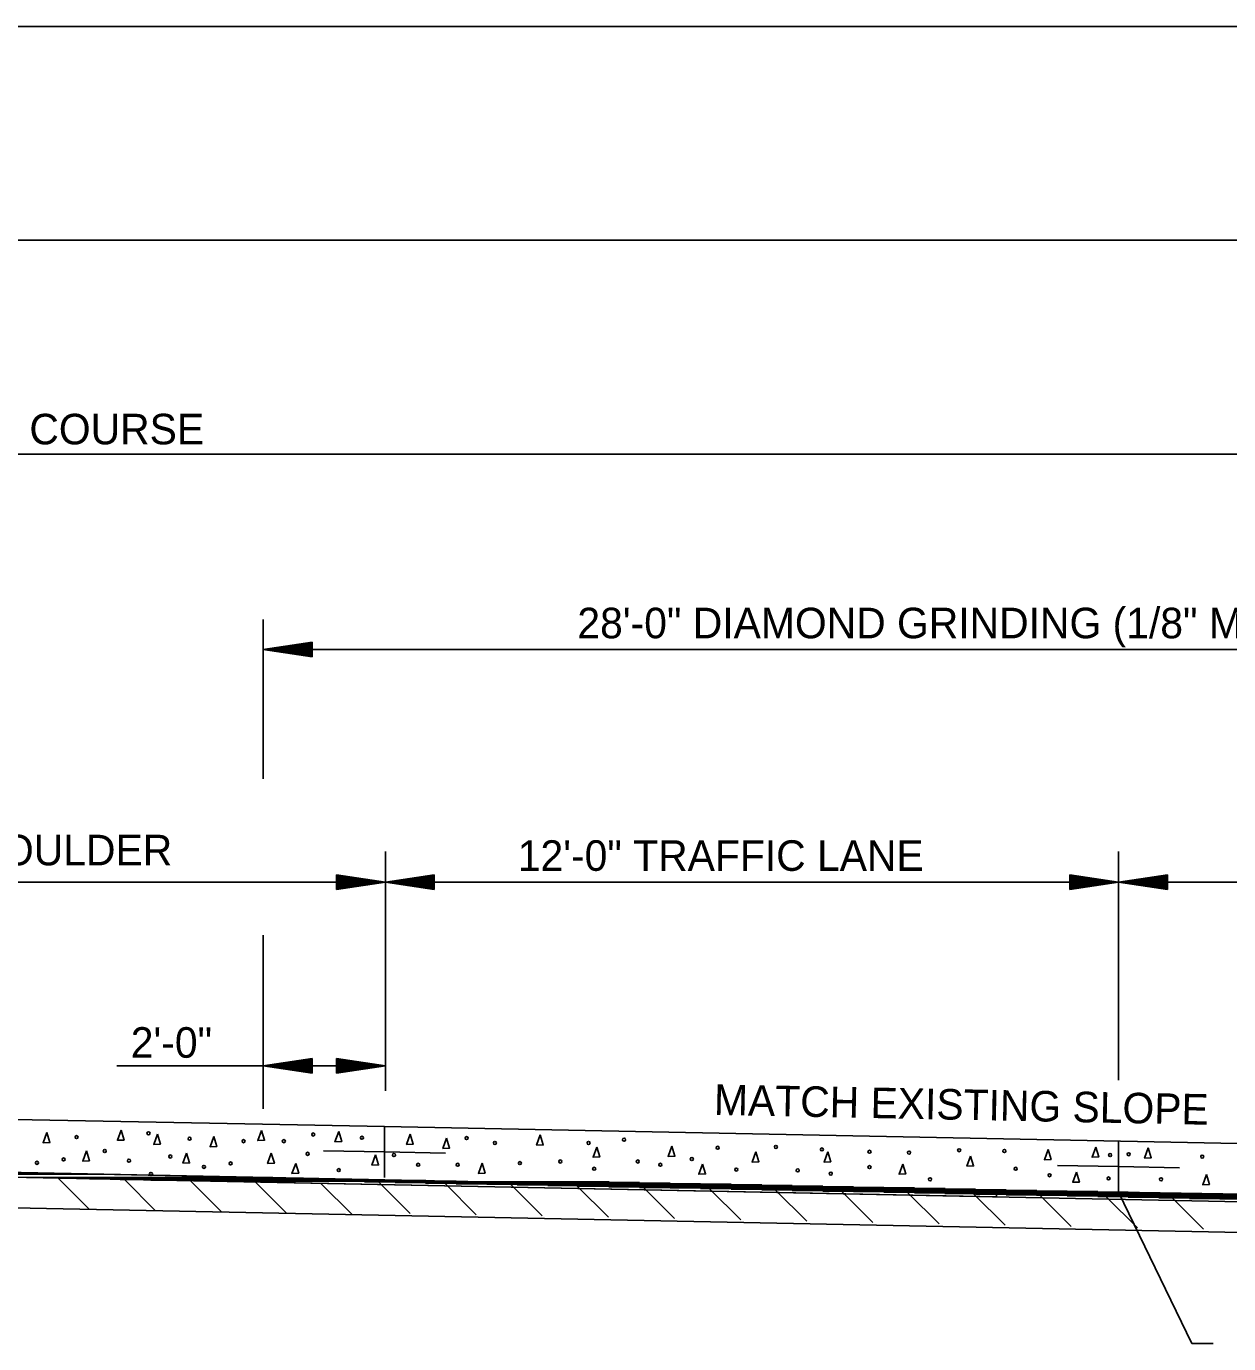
# Model space of a CAD drawing. Extents: x 60325 to 61047, y 53669 to 53767.
# Drawn here: x 60578.67 to 60598.35, y 53690.57 to 53712.12 of the extents above; entities that cross this region are included whole.
import ezdxf

# ---------------------------------------------------------------- set-up
doc = ezdxf.new("R2010")
doc.units = 0
doc.layers.add('R_Border', color=7, linetype='Continuous')
doc.layers.add('R_Border Prem', color=7, linetype='Continuous')

msp = doc.modelspace()

# ---------------------------------------------------------------- linework, layer by layer
at = {"layer": 'R_Border'}
for p, q in [((60582.545, 53699.814), (60582.545, 53702.419)), ((60583.345, 53702.049), (60582.545, 53701.929)), ((60583.345, 53702.029), (60582.679, 53701.929)), ((60583.345, 53701.809), (60583.345, 53702.049)), ((60610.545, 53701.929), (60582.545, 53701.929)), ((60583.345, 53701.809), (60582.545, 53701.929)), ((60583.345, 53701.829), (60582.679, 53701.929)), ((60583.345, 53702.009), (60582.816, 53701.929)), ((60583.345, 53701.85), (60582.816, 53701.929)), ((60583.345, 53701.989), (60582.95, 53701.929)), ((60583.345, 53701.87), (60582.95, 53701.929)), ((60583.345, 53701.969), (60583.085, 53701.929)), ((60583.345, 53701.891), (60583.085, 53701.929)), ((60583.345, 53701.948), (60583.219, 53701.929)), ((60583.345, 53701.911), (60583.219, 53701.929)), ((60584.545, 53694.884), (60584.545, 53698.624)), ((60596.545, 53694.884), (60596.545, 53698.624)), ((60583.745, 53698.244), (60584.545, 53698.124)), ((60583.745, 53698.244), (60583.745, 53698.004)), ((60583.745, 53698.224), (60584.412, 53698.124)), ((60583.745, 53698.204), (60584.274, 53698.124)), ((60583.745, 53698.184), (60584.141, 53698.124)), ((60583.745, 53698.163), (60584.005, 53698.124)), ((60583.745, 53698.143), (60583.872, 53698.124)), ((60585.345, 53698.244), (60584.545, 53698.124)), ((60585.345, 53698.224), (60584.679, 53698.124)), ((60585.345, 53698.204), (60584.816, 53698.124)), ((60585.345, 53698.184), (60584.95, 53698.124)), ((60585.345, 53698.164), (60585.085, 53698.124)), ((60585.345, 53698.143), (60585.219, 53698.124)), ((60585.345, 53698.004), (60585.345, 53698.244)), ((60595.745, 53698.244), (60596.545, 53698.124)), ((60595.745, 53698.244), (60595.745, 53698.004)), ((60595.745, 53698.224), (60596.412, 53698.124)), ((60595.745, 53698.204), (60596.274, 53698.124)), ((60595.745, 53698.184), (60596.141, 53698.124)), ((60595.745, 53698.163), (60596.005, 53698.124)), ((60595.745, 53698.143), (60595.872, 53698.124)), ((60597.345, 53698.244), (60596.545, 53698.124)), ((60597.345, 53698.224), (60596.679, 53698.124)), ((60597.345, 53698.204), (60596.816, 53698.124)), ((60597.345, 53698.184), (60596.95, 53698.124)), ((60597.345, 53698.164), (60597.085, 53698.124)), ((60597.345, 53698.143), (60597.219, 53698.124)), ((60597.345, 53698.004), (60597.345, 53698.244)), ((60572.545, 53698.124), (60584.545, 53698.124)), ((60583.745, 53698.004), (60584.545, 53698.124)), ((60583.745, 53698.085), (60584.005, 53698.124)), ((60583.745, 53698.045), (60584.274, 53698.124)), ((60583.745, 53698.024), (60584.412, 53698.124)), ((60583.745, 53698.065), (60584.141, 53698.124)), ((60583.745, 53698.106), (60583.872, 53698.124)), ((60585.345, 53698.004), (60584.545, 53698.124)), ((60596.545, 53698.124), (60584.545, 53698.124)), ((60585.345, 53698.024), (60584.679, 53698.124)), ((60585.345, 53698.045), (60584.816, 53698.124)), ((60585.345, 53698.065), (60584.95, 53698.124)), ((60585.345, 53698.086), (60585.085, 53698.124)), ((60585.345, 53698.106), (60585.219, 53698.124)), ((60595.745, 53698.004), (60596.545, 53698.124)), ((60595.745, 53698.085), (60596.005, 53698.124)), ((60595.745, 53698.045), (60596.274, 53698.124)), ((60595.745, 53698.024), (60596.412, 53698.124)), ((60595.745, 53698.065), (60596.141, 53698.124)), ((60595.745, 53698.106), (60595.872, 53698.124)), ((60608.545, 53698.124), (60596.545, 53698.124)), ((60597.345, 53698.004), (60596.545, 53698.124)), ((60597.345, 53698.024), (60596.679, 53698.124)), ((60597.345, 53698.045), (60596.816, 53698.124)), ((60597.345, 53698.065), (60596.95, 53698.124)), ((60597.345, 53698.086), (60597.085, 53698.124)), ((60597.345, 53698.106), (60597.219, 53698.124)), ((60582.545, 53694.411), (60582.545, 53697.257)), ((60584.545, 53694.709), (60584.545, 53695.444)), ((60582.545, 53695.118), (60580.151, 53695.118)), ((60583.345, 53695.238), (60582.545, 53695.118)), ((60584.545, 53695.118), (60582.545, 53695.118)), ((60583.345, 53694.998), (60582.545, 53695.118)), ((60583.345, 53695.218), (60582.679, 53695.118)), ((60583.345, 53695.018), (60582.679, 53695.118)), ((60583.345, 53695.197), (60582.816, 53695.118)), ((60583.345, 53695.038), (60582.816, 53695.118)), ((60583.345, 53695.177), (60582.95, 53695.118)), ((60583.345, 53695.058), (60582.95, 53695.118)), ((60583.345, 53695.156), (60583.085, 53695.118)), ((60583.345, 53695.078), (60583.085, 53695.118)), ((60583.345, 53695.136), (60583.219, 53695.118)), ((60583.345, 53695.099), (60583.219, 53695.118)), ((60583.345, 53695.238), (60583.345, 53694.998)), ((60583.745, 53695.238), (60584.545, 53695.118)), ((60583.745, 53695.238), (60583.745, 53694.998)), ((60583.745, 53695.218), (60584.412, 53695.118)), ((60583.745, 53695.197), (60584.274, 53695.118)), ((60583.745, 53695.177), (60584.141, 53695.118)), ((60583.745, 53695.156), (60584.005, 53695.118)), ((60583.745, 53695.136), (60583.872, 53695.118)), ((60583.745, 53694.998), (60584.545, 53695.118)), ((60583.745, 53695.078), (60584.005, 53695.118)), ((60583.745, 53695.038), (60584.274, 53695.118)), ((60583.745, 53695.018), (60584.412, 53695.118)), ((60583.745, 53695.058), (60584.141, 53695.118)), ((60583.745, 53695.099), (60583.872, 53695.118)), ((60584.53, 53694.125), (60584.53, 53693.292)), ((60596.545, 53693.884), (60596.545, 53693.051)), ((60583.53, 53693.728), (60584.53, 53693.708)), ((60584.53, 53693.708), (60585.53, 53693.688)), ((60595.545, 53693.488), (60596.545, 53693.468)), ((60596.545, 53693.468), (60597.545, 53693.448)), ((60597.746, 53690.571), (60596.545, 53693.051)), ((60598.093, 53690.571), (60597.746, 53690.571))]:
    msp.add_line(p, q, dxfattribs=at)
msp.add_lwpolyline([(60582.532, 53694.162), (60584.53, 53694.125), (60610.545, 53693.604)], dxfattribs=at)
at = {"layer": 'R_Border Prem'}
for p, q in [((60618.545, 53712.124), (60524.545, 53712.124)), ((60619.713, 53708.624), (60522.149, 53708.624)), ((60619.713, 53705.124), (60522.149, 53705.124)), ((60582.532, 53694.162), (60572.541, 53694.344)), ((60571.545, 53693.511), (60610.545, 53692.731)), ((60571.545, 53693.431), (60610.545, 53692.651)), ((60575.4, 53693.354), (60579.401, 53693.354)), ((60575.9, 53693.344), (60579.901, 53693.344)), ((60578.704, 53693.288), (60582.705, 53693.288)), ((60579.191, 53693.278), (60579.702, 53692.768)), ((60579.204, 53693.278), (60583.205, 53693.278)), ((60579.704, 53693.268), (60583.705, 53693.268)), ((60580.204, 53693.258), (60584.205, 53693.258)), ((60580.274, 53693.256), (60580.784, 53692.746)), ((60580.704, 53693.248), (60584.705, 53693.248)), ((60581.204, 53693.238), (60585.205, 53693.238)), ((60581.356, 53693.235), (60581.866, 53692.724)), ((60581.704, 53693.228), (60585.705, 53693.228)), ((60582.421, 53693.213), (60582.932, 53692.703)), ((60583.49, 53693.192), (60584.001, 53692.682)), ((60584.204, 53693.218), (60588.205, 53693.218)), ((60584.443, 53693.209), (60584.949, 53692.703)), ((60584.704, 53693.208), (60588.705, 53693.208)), ((60585.204, 53693.198), (60589.205, 53693.198)), ((60585.521, 53693.191), (60586.031, 53692.681)), ((60585.704, 53693.188), (60589.705, 53693.188)), ((60586.204, 53693.178), (60590.205, 53693.178)), ((60586.603, 53693.17), (60587.113, 53692.66)), ((60586.704, 53693.168), (60590.705, 53693.168)), ((60587.204, 53693.158), (60591.205, 53693.158)), ((60587.685, 53693.148), (60588.196, 53692.638)), ((60587.704, 53693.148), (60591.705, 53693.148)), ((60588.204, 53693.138), (60592.205, 53693.138)), ((60588.704, 53693.128), (60592.705, 53693.128)), ((60588.768, 53693.127), (60589.278, 53692.616)), ((60589.204, 53693.118), (60593.205, 53693.118)), ((60589.704, 53693.108), (60593.705, 53693.108)), ((60589.85, 53693.105), (60590.36, 53692.595)), ((60590.204, 53693.098), (60594.205, 53693.098)), ((60590.704, 53693.088), (60594.705, 53693.088)), ((60590.932, 53693.083), (60591.443, 53692.573)), ((60591.204, 53693.078), (60595.205, 53693.078)), ((60591.704, 53693.068), (60595.705, 53693.068)), ((60592.015, 53693.062), (60592.525, 53692.551)), ((60592.204, 53693.058), (60596.205, 53693.058)), ((60592.704, 53693.048), (60596.705, 53693.048)), ((60593.097, 53693.04), (60593.607, 53692.53)), ((60593.204, 53693.038), (60597.205, 53693.038)), ((60593.704, 53693.028), (60597.705, 53693.028)), ((60594.179, 53693.018), (60594.689, 53692.508)), ((60594.204, 53693.018), (60598.205, 53693.018)), ((60594.704, 53693.008), (60598.705, 53693.008)), ((60595.204, 53692.998), (60599.205, 53692.998)), ((60595.261, 53692.997), (60595.772, 53692.486)), ((60595.704, 53692.988), (60599.705, 53692.988)), ((60596.204, 53692.978), (60600.205, 53692.978)), ((60596.344, 53692.975), (60596.854, 53692.465)), ((60596.704, 53692.968), (60600.705, 53692.968)), ((60571.545, 53692.931), (60610.502, 53692.152)), ((60597.204, 53692.958), (60601.205, 53692.958)), ((60597.426, 53692.953), (60597.936, 53692.443)), ((60597.704, 53692.948), (60601.705, 53692.948)), ((60598.204, 53692.938), (60602.205, 53692.938))]:
    msp.add_line(p, q, dxfattribs=at)
for points in [[(60580.219, 53694.064), (60580.158, 53693.898), (60580.268, 53693.903), (60580.219, 53694.064)], [(60582.518, 53694.059), (60582.457, 53693.893), (60582.567, 53693.898), (60582.518, 53694.059)], [(60583.781, 53694.04), (60583.72, 53693.874), (60583.83, 53693.878), (60583.781, 53694.04)], [(60579.004, 53694.024), (60578.943, 53693.858), (60579.053, 53693.862), (60579.004, 53694.024)], [(60580.813, 53693.998), (60580.753, 53693.832), (60580.863, 53693.837), (60580.813, 53693.998)], [(60581.737, 53693.958), (60581.676, 53693.792), (60581.786, 53693.796), (60581.737, 53693.958)], [(60584.952, 53693.998), (60584.891, 53693.832), (60585.001, 53693.837), (60584.952, 53693.998)], [(60585.547, 53693.932), (60585.486, 53693.766), (60585.596, 53693.771), (60585.547, 53693.932)], [(60587.08, 53693.985), (60587.019, 53693.819), (60587.129, 53693.823), (60587.08, 53693.985)], [(60579.652, 53693.724), (60579.591, 53693.558), (60579.701, 53693.563), (60579.652, 53693.724)], [(60581.291, 53693.69), (60581.231, 53693.524), (60581.341, 53693.529), (60581.291, 53693.69)], [(60582.678, 53693.685), (60582.618, 53693.519), (60582.728, 53693.523), (60582.678, 53693.685)], [(60584.385, 53693.658), (60584.324, 53693.492), (60584.434, 53693.496), (60584.385, 53693.658)], [(60588.005, 53693.787), (60587.944, 53693.621), (60588.054, 53693.625), (60588.005, 53693.787)], [(60589.234, 53693.8), (60589.173, 53693.634), (60589.283, 53693.638), (60589.234, 53693.8)], [(60590.608, 53693.707), (60590.548, 53693.541), (60590.658, 53693.546), (60590.608, 53693.707)], [(60591.784, 53693.707), (60591.724, 53693.541), (60591.834, 53693.546), (60591.784, 53693.707)], [(60594.124, 53693.641), (60594.063, 53693.475), (60594.173, 53693.48), (60594.124, 53693.641)], [(60595.392, 53693.747), (60595.332, 53693.581), (60595.442, 53693.586), (60595.392, 53693.747)], [(60596.172, 53693.787), (60596.112, 53693.621), (60596.222, 53693.625), (60596.172, 53693.787)], [(60597.031, 53693.773), (60596.971, 53693.607), (60597.081, 53693.612), (60597.031, 53693.773)], [(60583.077, 53693.52), (60583.016, 53693.354), (60583.126, 53693.358), (60583.077, 53693.52)], [(60586.128, 53693.522), (60586.068, 53693.356), (60586.178, 53693.361), (60586.128, 53693.522)], [(60589.736, 53693.509), (60589.675, 53693.343), (60589.785, 53693.348), (60589.736, 53693.509)], [(60593.013, 53693.509), (60592.953, 53693.343), (60593.063, 53693.348), (60593.013, 53693.509)], [(60595.855, 53693.377), (60595.794, 53693.211), (60595.904, 53693.215), (60595.855, 53693.377)], [(60597.983, 53693.337), (60597.922, 53693.171), (60598.032, 53693.176), (60597.983, 53693.337)]]:
    msp.add_lwpolyline(points, dxfattribs=at)
for points in [[(60571.545, 53693.511), (60594.545, 53693.051), (60594.545, 53692.971), (60571.545, 53693.431)], [(60596.541, 53692.979), (60596.545, 53693.051), (60610.545, 53692.826), (60610.545, 53692.731)]]:
    msp.add_lwpolyline(points, close=True, dxfattribs=at)
for centre in [(60579.49, 53693.95), (60580.668, 53694.013), (60581.34, 53693.924), (60582.223, 53693.884), (60582.883, 53693.884), (60583.364, 53693.993), (60584.161, 53693.939), (60585.874, 53693.934), (60586.337, 53693.855), (60587.87, 53693.855), (60588.451, 53693.908), (60579.279, 53693.585), (60579.952, 53693.723), (60581.024, 53693.633), (60583.272, 53693.677), (60584.685, 53693.657), (60589.561, 53693.591), (60589.984, 53693.776), (60590.936, 53693.789), (60591.689, 53693.749), (60592.469, 53693.71), (60593.116, 53693.697), (60593.936, 53693.736), (60594.676, 53693.723), (60596.407, 53693.657), (60596.711, 53693.67), (60597.914, 53693.631), (60578.842, 53693.529), (60580.348, 53693.564), (60581.575, 53693.463), (60582.012, 53693.519), (60583.782, 53693.41), (60585.081, 53693.498), (60585.729, 53693.498), (60586.746, 53693.525), (60587.407, 53693.551), (60587.962, 53693.432), (60588.676, 53693.551), (60589.046, 53693.498), (60590.288, 53693.419), (60591.293, 53693.406), (60592.469, 53693.459), (60594.861, 53693.432), (60580.708, 53693.349), (60591.835, 53693.353), (60593.46, 53693.26), (60595.416, 53693.327), (60596.381, 53693.274), (60597.24, 53693.26)]:
    msp.add_circle(centre, 0.025, dxfattribs=at)

# ---------------------------------------------------------------- texts
at = {"layer": 'R_Border'}
for s, p in [('28\'-0" DIAMOND GRINDING (1/8" MIN. DEPTH) S.B.', (60587.687, 53702.112)), ('10\'-0" SHOULDER', (60575.452, 53698.397)), ('12\'-0" TRAFFIC LANE', (60586.712, 53698.307)), ('2\'-0"', (60580.377, 53695.249))]:
    msp.add_text(s, height=0.5, dxfattribs=at).set_placement(p)
msp.add_text('MATCH EXISTING SLOPE', height=0.5, rotation=358.8542, dxfattribs=at).set_placement((60589.919, 53694.314))
at = {"layer": 'R_Border Prem'}
msp.add_text('EXISTING 96\'-8" CEMENT STABILIZED CRUSHED STONE BASE COURSE', height=0.5, dxfattribs=at).set_placement((60558.55, 53705.285))

doc.saveas('drawing.dxf')
